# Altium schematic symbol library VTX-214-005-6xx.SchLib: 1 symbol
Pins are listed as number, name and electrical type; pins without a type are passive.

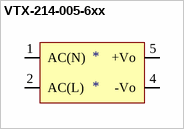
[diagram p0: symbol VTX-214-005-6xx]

## VTX-214-005-6xx
designator *
footprint VTX-214-005-6xx (Footprint not found)
pins: 1 AC(N), 2 AC(L), 4 -Vo, 5 +Vo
